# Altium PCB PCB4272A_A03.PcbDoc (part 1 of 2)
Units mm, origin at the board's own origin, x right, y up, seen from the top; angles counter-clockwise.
Board outline 32 x 51 mm, 4 copper layers (Top Layer, Signal Layer 2, Signal Layer 3, Bottom Layer), stack 1.6 mm thick; 110 components, 91 nets, 408 pads, 551 vias.
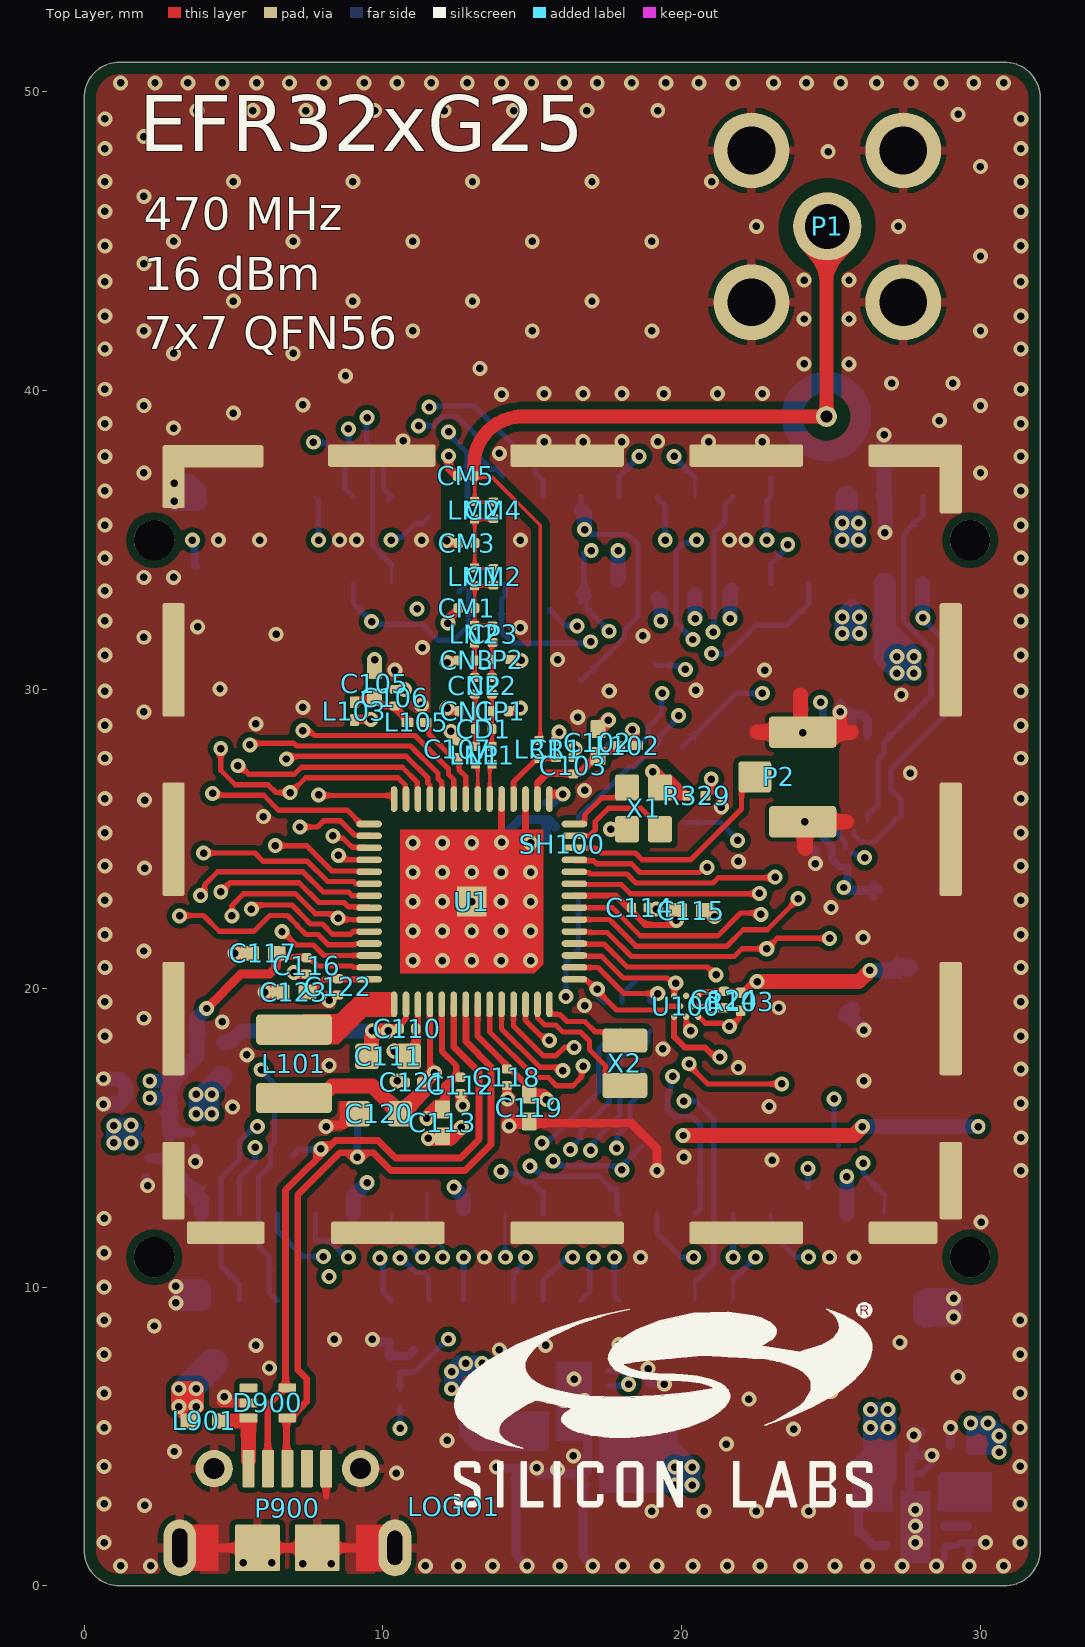
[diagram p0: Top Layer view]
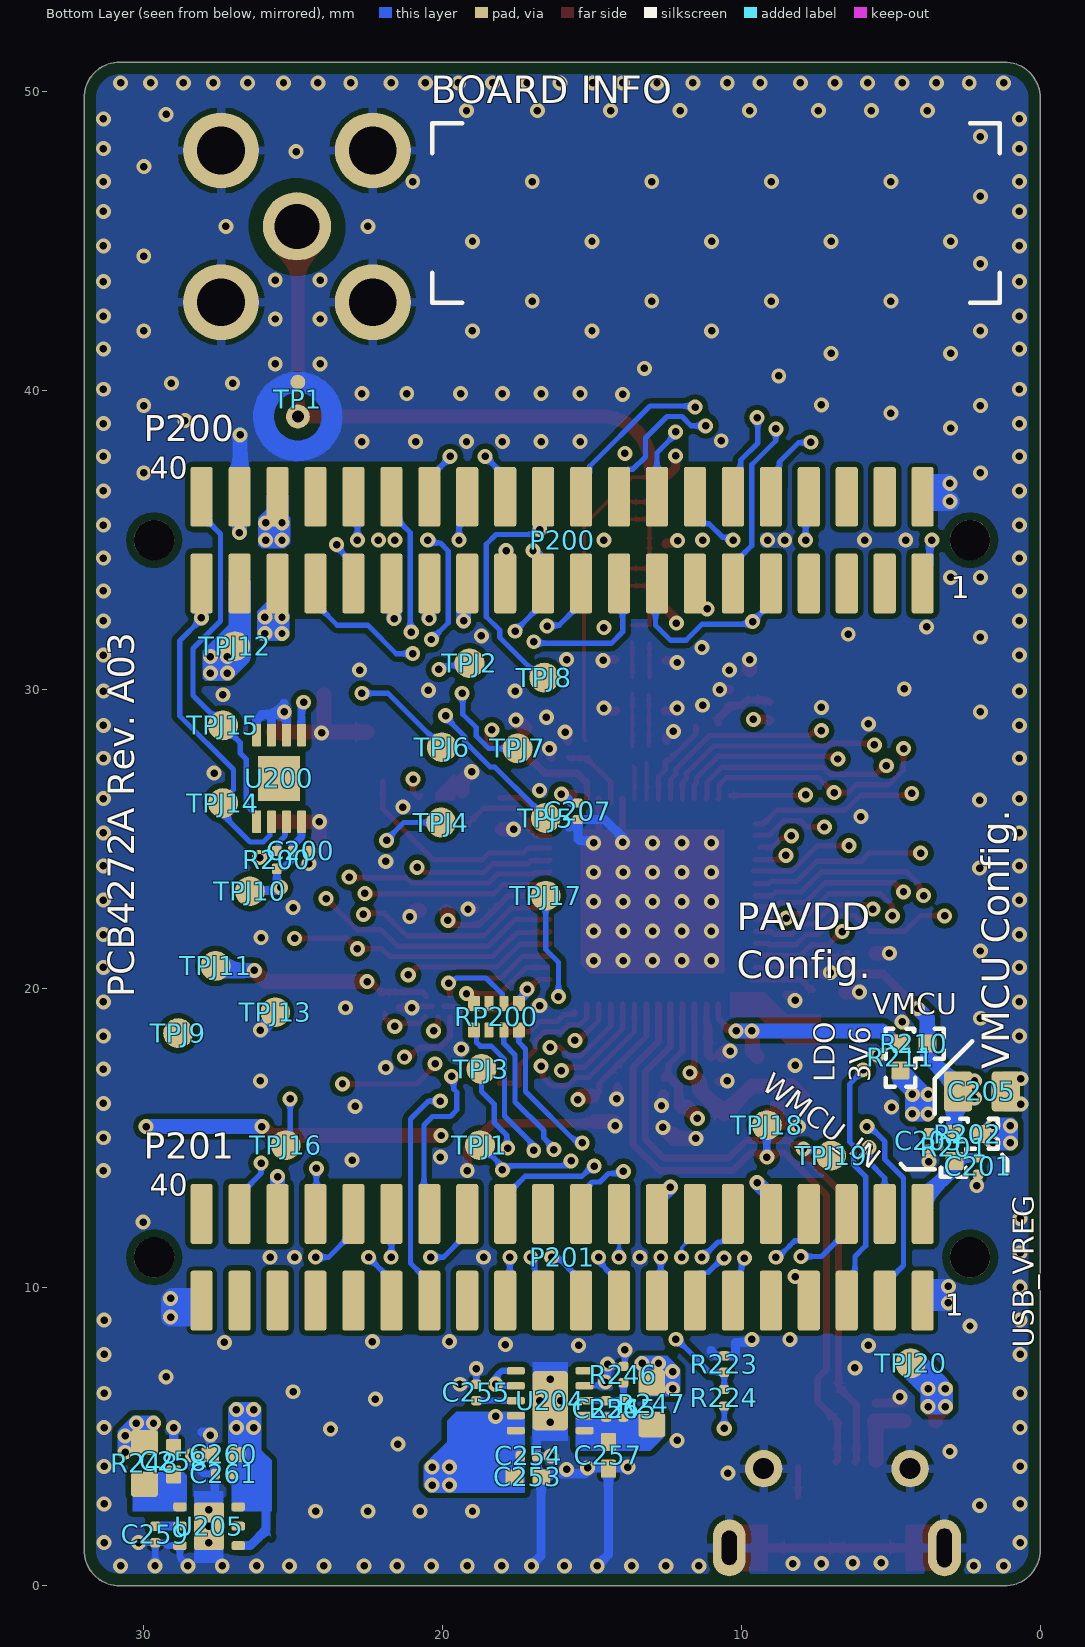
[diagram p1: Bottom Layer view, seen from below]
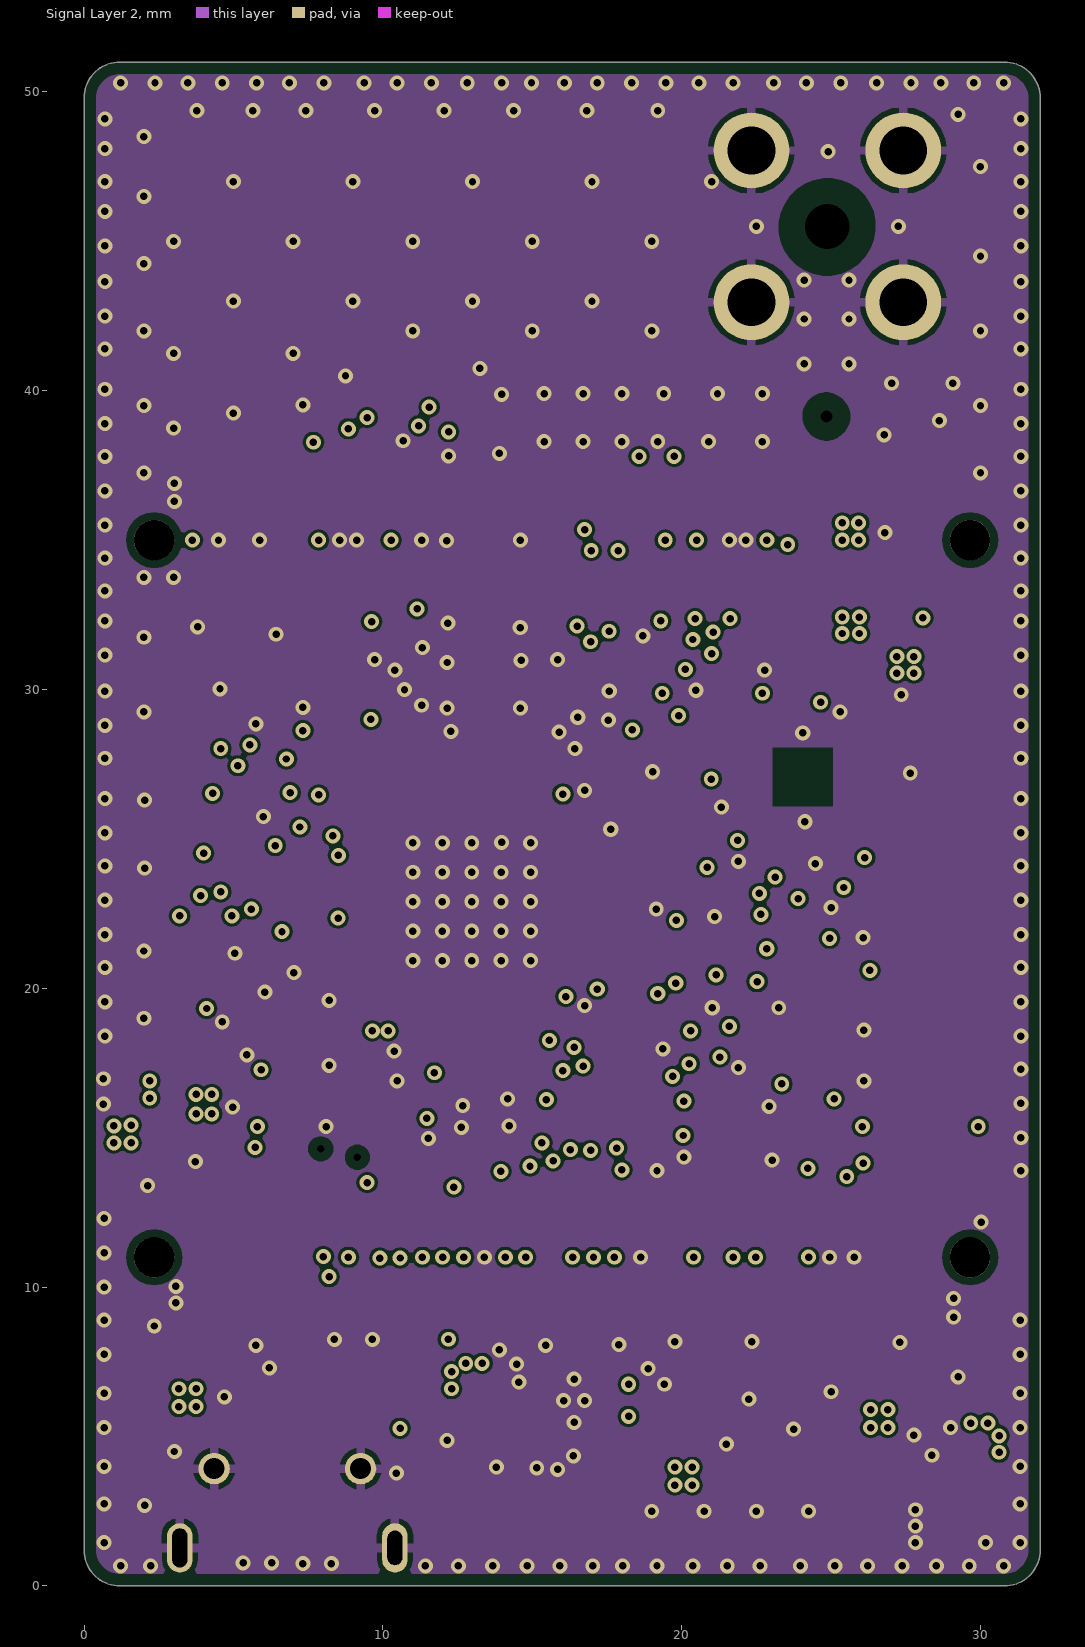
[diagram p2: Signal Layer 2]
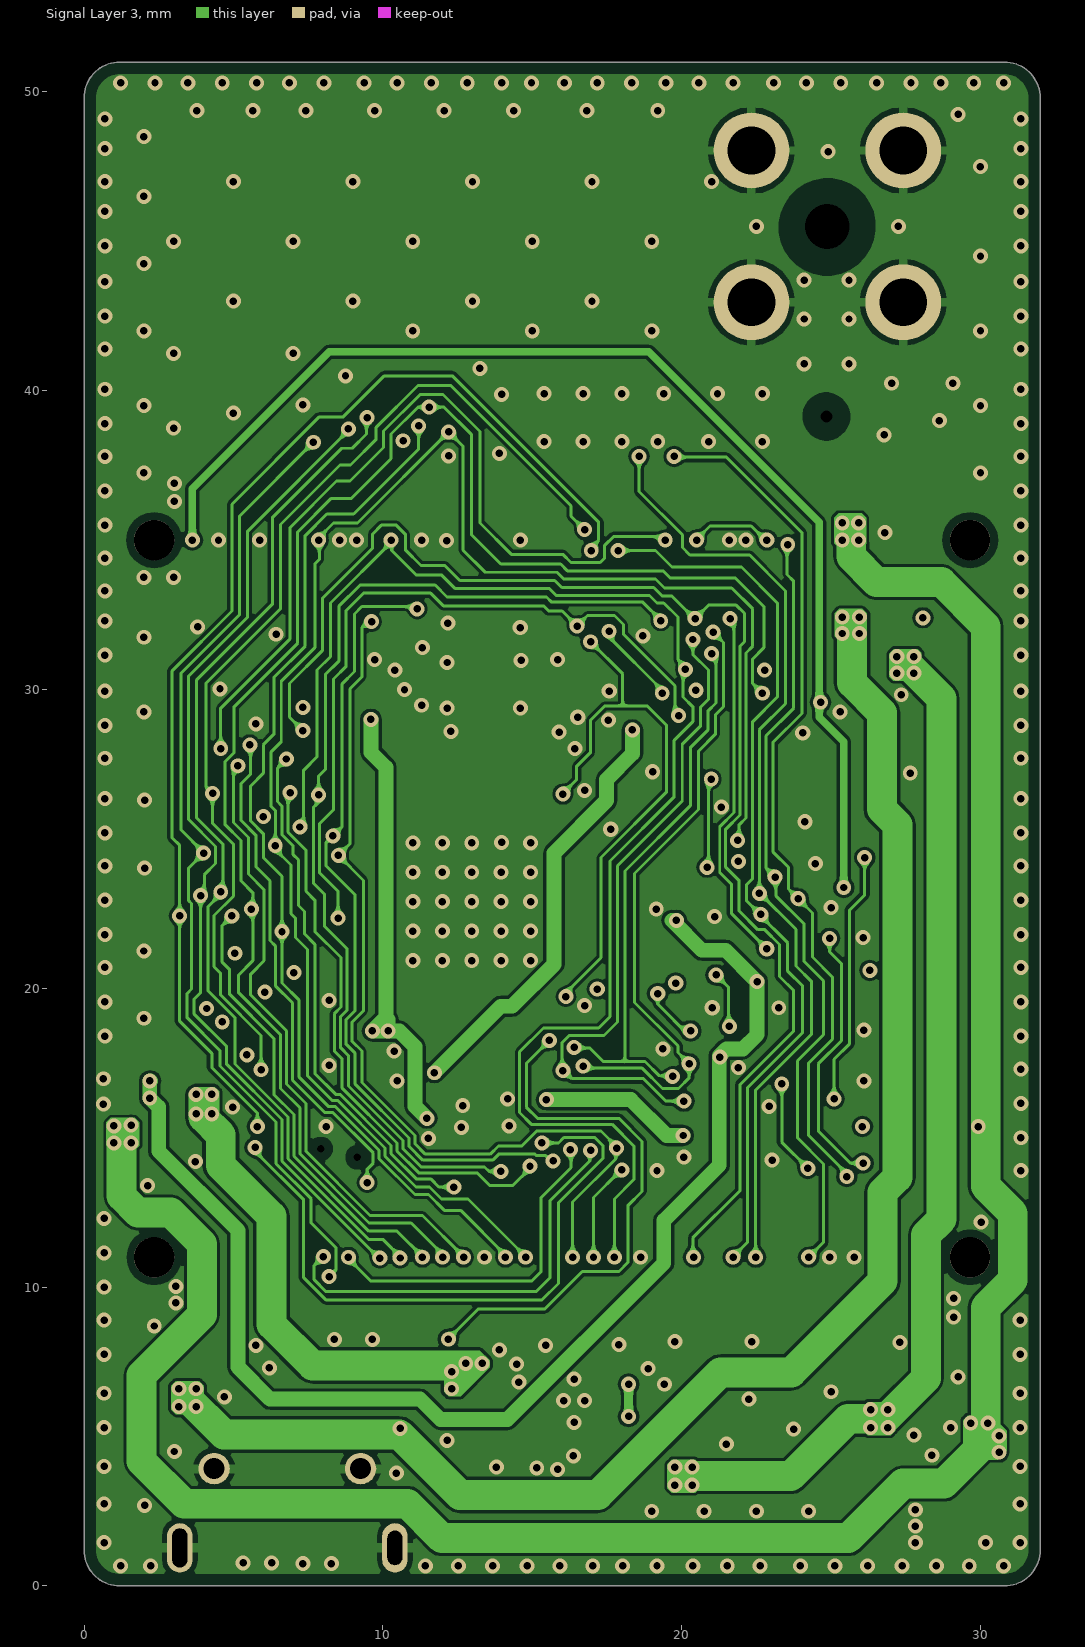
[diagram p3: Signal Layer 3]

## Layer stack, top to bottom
Top Solder: solder mask 0.0102, Solder Resist, Dk 3.5
Top Layer: signal copper 0.035
Dielectric 1: core 0.325, FR-4, Dk 4.2
Signal Layer 2: signal copper 0.018
Dielectric 3: prepreg 0.844, Dk 4.2
Signal Layer 3: signal copper 0.018
Dielectric 2: core 0.325, Dk 4.2
Bottom Layer: signal copper 0.035
Bottom Solder: solder mask 0.0102, Solder Resist, Dk 3.5

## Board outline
0,1.2 ccw(c1.2,1.2) 1.2,0 30.8,0 ccw(c30.8,1.2) 32,1.2 32,49.8 ccw(c30.8,49.8) 30.8,51 1.2,51 ccw(c1.2,49.8) 0,49.8

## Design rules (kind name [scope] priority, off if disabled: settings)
AcuteAngle [All] p1: minimum=7.00000000000000E+0001 checktracksonly=FALSE
BoardOutlineClearance [All] p1: gap=0.4 ignorepadtopadclearanceinfootprint=FALSE
Clearance [IsVia vs IsVia] p1: gap=0.175 ignorepadtopadclearanceinfootprint=FALSE except(0: Arc-Hole Track-Hole SMDPad-Hole THPad-Hole Via-Hole Fill-Hole Poly-Hole Region-Hole Text-Hole)
Clearance Clearance_50Ohm [InNetClass('50Ohm') vs InNet('GND')] p2: gap=0.254 ignorepadtopadclearanceinfootprint=FALSE except(0: Arc-Hole Track-Hole SMDPad-Hole THPad-Hole Via-Hole Fill-Hole Poly-Hole Region-Hole Text-Hole; 0.15: Track-SMDPad; 0.2: SMDPad-SMDPad)
Clearance Clearance_to_Holes [InPadClass('NPTH')] p3: gap=0.254 ignorepadtopadclearanceinfootprint=FALSE except(0: Arc-Hole Track-Hole SMDPad-Hole THPad-Hole Via-Hole Fill-Hole Poly-Hole Region-Hole Text-Hole)
Clearance Clearance_Outer_Layers [All vs OnLayer('Top Layer') or OnLayer('Bottom Layer')] p4: gap=0.175 ignorepadtopadclearanceinfootprint=FALSE except(0: Arc-Hole Track-Hole SMDPad-Hole THPad-Hole Via-Hole Fill-Hole Poly-Hole Region-Hole Text-Hole)
Clearance Clearance_Inner_Layers [All vs OnLayer('Signal Layer 2') or OnLayer('Signal Layer 3')] p5: gap=0.1 ignorepadtopadclearanceinfootprint=FALSE except(0: Arc-Hole Track-Hole SMDPad-Hole THPad-Hole Via-Hole Fill-Hole Poly-Hole Region-Hole Text-Hole; 0.175: Via-Via)
HoleToHoleClearance HoleToHoleClearance_ANT1toPAD [Incomponent ('ANT1') vs ISpad] p1: gap=0 allowstackedmicrovias=TRUE
HoleToHoleClearance HoleToHoleClearance_R1toR2_1 [Incomponent ('R1') vs Incomponent ('R2')] p2: gap=0 allowstackedmicrovias=TRUE
HoleToHoleClearance HoleToHoleClearance_U1toVIA_1 [InComponent ('U1') vs IsVia] p3: gap=0 allowstackedmicrovias=TRUE
HoleToHoleClearance [All] p4: gap=0.254 allowstackedmicrovias=TRUE
MinimumSolderMaskSliver [All] p1: minsoldermaskwidth=0.075
PolygonConnect Polygon_VIA_Connect [IsVia] p1: connectstyle=Direct reliefconductorwidth=0.254 reliefentries=4 polygonreliefangle="90 Angle" airgapwidth=0.254
PolygonConnect PolygonConnect_SH100 [InComponent('SH100')] p2: connectstyle=Direct reliefconductorwidth=0.254 reliefentries=4 polygonreliefangle="90 Angle" airgapwidth=0.127
PolygonConnect PolygonConnect_P1 [InComponent('P1') or InComponent('P900')] p3: connectstyle=Relief reliefconductorwidth=0.3 reliefentries=4 polygonreliefangle="90 Angle" airgapwidth=0.175
PolygonConnect [All] p4: connectstyle=NoConnect reliefconductorwidth=0.2 reliefentries=4 polygonreliefangle="90 Angle" airgapwidth=0.125
RoutingVias [All] p1: holewidth=0.3 width=0.65 viastyle="Through Hole" minholewidth=0.25 minwidth=0.5 maxholewidth=1 maxwidth=1.5
ShortCircuit ShortCircuit_ANTtoPAD [InNet('NetAT1_1') vs InNet('GND')] p1: allowed=TRUE
ShortCircuit ShortCircuit_R1toR2_1 [Incomponent ('R1') vs Incomponent ('R2')] p2: allowed=TRUE
ShortCircuit [All] p3: allowed=FALSE
SilkToSilkClearance [All] p1: silktosilkclearance=0.102
SilkToSolderMaskClearance [IsPad] p1: minsilkscreentomaskgap=0.102 clearancetoexposedcopper=TRUE
SolderMaskExpansion [All] p1: expansion=0.051 istentingtop=FALSE
Width 50ohm [InNet('50R*')] p1: maxlimit=0.457 minlimit=0.124 preferedwidth=0.457
Width [All] p2: maxlimit=5.08 minlimit=0.1 preferedwidth=0.125
25 further rules are at their usual default settings.

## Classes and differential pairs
pad class NPTH: P200-M1 P200-M2 P201-M1 P201-M2
net class 50Ohm: 50R_P1

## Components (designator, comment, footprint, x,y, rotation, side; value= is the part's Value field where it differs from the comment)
C102 "1U" C0402_L 17.2,28.225 r90 top
C103 "100P" C0201_L 16.375,27.45 r90 top
C105 "470N" C0402_L 9.725,30.2 r90 top
C106 "100P" C0201_L 10.4,29.725 r90 top
C107 "100P" C0201_L 12.5,28 r90 top
C110 "100N" C0201_L 10.825,18.65 r0 top
C111 "10U" C0603_L 10.175,17.725 r0 top
C112 "10N" C0201_L 12.6,16.75 r270 top
C113 "1U" C0402_L 12,15.5 r270 top
C114 "100N" C0201_L 18.6,22.7 r0 top
C115 "1U" C0402_L 20.325,22.6 r0 top
C116 "100N" C0201_L 7.45,20.75 r270 top
C117 "1U" C0402_L 6,21.175 r180 top
C118 "100N" C0201_L 14.15,17.025 r270 top
C119 "1U" C0402_L 14.9,16 r270 top
C120 "4U7" C0603_L 9.875,15.8 r180 top
C121 "100N" C0201_L 11.025,16.85 r180 top
C122 "100N" C0201_L 8.5,20.05 r270 top
C123 "1U" C0402_L 7.025,19.875 r180 top
C124 "100N" C0201_L 21.425,19.625 r270 top
C200 "100N" C0201_L 24.75,24.6 r180 bottom
C201 "100N" C0201_L 2.075,14.05 r270 bottom
C203 "100N" C0201_L 3.725,14.9 r270 bottom
C205 "10U" C0805_L 1.95,16.55 r180 bottom
C207 "100N" C0201_L 15.475,25.925 r270 bottom
C253 "1U" C0402_L 17.15,3.65 r180 bottom
C254 "100N" C0201_L 17.125,4.35 r180 bottom
C255 "100N" C0201_L 18.875,6.475 r90 bottom
C256 "10N" C0201_L 14.525,5.925 r90 bottom
C257 "10U" C0402_L 14.45,4.375 r270 bottom
C258 "2U2" C0402_L 29,4.175 r90 bottom
C259 "100N" C0201_L 29.615,1.725 r270 bottom
C260 "1U" C0402_L 27.325,4.4 r0 bottom
C261 "100N" C0201_L 27.325,3.75 r0 bottom
CD1 "Unused" C0201_L 13.375,28.675 r0 top
CM1 "8P0" C0201_L 12.8,32.725 r180 top
CM2 "Unused" C0201_L 13.7,33.775 r90 top
CM3 "9P5" C0201_L 12.8,34.9 r180 top
CM4 "Unused" C0201_L 13.7,36 r90 top
CM5 "5P0" C0201_L 12.775,37.15 r180 top
CN1 "18P" C0201_L 12.825,29.275 r180 top
CN2 "220P" C0201_L 13.075,30.125 r90 top
CN3 "9P0" C0201_L 12.8,30.975 r0 top
CP1 "20P" C0201_L 13.925,29.275 r0 top
CP2 "220P" C0201_L 13.65,30.125 r270 top
CP3 "7P0" C0201_L 13.675,31.85 r270 top
CR1 "Unused" C0201_L 15.8,27.997 r90 top
D900 "SP1001-04" SOT553_L 6.15,6.125 r0 top
Designator39 "Comment" PCB_SPEC_4_LAYER -67.7,114.2 r0 top
L101 "2U2" COIL_1008_L 7.025,17.475 r270 top
L102 "BLM03AG700SN1D" COIL_MUR_BLM03_0201 18.2,28.125 r180 top
L103 "0R" COIL_MUR_BLM03_0201 9.05,29.275 r90 top
L105 "BLM03PG330SN1D" COIL_MUR_BLM03_0201 11.125,28.9 r0 top
L901 "782422221" COIL_0402 4.025,5.525 r180 top
LM1 "13N" COIL_0201_L 13.075,33.775 r90 top
LM2 "16N" COIL_0201_L 13.075,36 r90 top
LN1 "4N2" COIL_0201_L 13.1,27.8 r90 top
LN2 "16N" COIL_0201_L 13.075,31.85 r90 top
LOGO1 "Comment" LOGO_SILABS_W14.0 12.375,2.65 r0 top
LP1 "4N2" COIL_0201_L 13.65,27.8 r90 top
LP2 "16N" COIL_0201_L 13.95,31 r180 top
LR1 "68N" COIL_0201_L 15.225,27.997 r90 top
P1 "SMA" TE_SMA_1814832_TH_VER 24.875,45.5 r0 top
P2 "U.FL" HIROSE_U.FL-R-SMT-1 24.05,27.075 r90 top
P200 "SOCKET_WCON_2X20_1.27MM_SMD" SAM_SFC-120-T2-D-A-2X20_SNUM 16,35 r0 bottom locked
P201 "SOCKET_WCON_2X20_1.27MM_SMD" SAM_SFC-120-T2-D-A-2X20_SNUM 16,11 r0 bottom locked
P900 "USB MICRO-B" KLS_L-KLS1-238-0-X-0-X 6.805,-0.475 r0 top
R103 "330K" R0201_L#1 21.975,19.55 r90 top
R200 "10K" R0201_L#1 25.55,24.3 r270 bottom
R201 "0R" R0402_L 2.875,14.675 r270 bottom
R202 "0R" R0402_L 2.425,15.125 r180 bottom
R210 "0R" R0402_L 4.225,18.15 r0 bottom
R211 "0R" R0402_L 4.675,17.7 r90 bottom
R223 "680K" R0201_L#2 10.575,7.425 r270 bottom
R224 "390K" R0201_L#2 10.575,6.3 r270 bottom
R245 "4.02k" R0201_L#2 13.95,5.925 r270 bottom
R246 "1.15k" R0201_L#2 13.95,7.075 r270 bottom
R247 "0R" R0603_L 13,6.1 r90 bottom
R248 "0R" R0603_L 29.975,4.1 r90 bottom
R329 "100K" R0201_L#1 20.5,26.45 r180 top
RP200 "100R" RES_MNR04-8 18.2,19.05 r0 bottom
SH100 "RF_SHIELD_FRAME_BMI-S-203-F" RF_SHIELD_FRAME_BMI-S-203-F_PCB4270 16,24.825 r0 top locked
TP1 "TP_RF" "TP_INGUN_50_OHM_CLOSED OPENVIA" 24.845,39.135 r0 bottom
TPJ1 "TPJ_SMD" TP_1.0_SMD 18.75,14.75 r90 bottom locked
TPJ2 "TPJ_SMD" TP_1.0_SMD 19.1,30.88 r90 bottom locked
TPJ3 "TPJ_SMD" TP_1.0_SMD 18.7,17.3 r90 bottom locked
TPJ4 "TPJ_SMD" TP_1.0_SMD 20.05,25.55 r90 bottom locked
TPJ5 "TPJ_SMD" TP_1.0_SMD 16.55,25.7 r90 bottom locked
TPJ6 "TPJ_SMD" TP_1.0_SMD 20.02,28.07 r90 bottom locked
TPJ7 "TPJ_SMD" TP_1.0_SMD 17.49,28.03 r90 bottom locked
TPJ8 "TPJ_SMD" TP_1.0_SMD 16.6,30.4 r90 bottom locked
TPJ9 "TPJ_SMD" TP_1.0_SMD 28.85,18.5 r90 bottom locked
TPJ10 "TPJ_SMD" TP_1.0_SMD 26.45,23.25 r90 bottom locked
TPJ11 "TPJ_SMD" TP_1.0_SMD 27.6,20.75 r90 bottom locked
TPJ12 "TPJ_SMD" TP_1.0_SMD 26.95,31.45 r90 bottom locked
TPJ13 "TPJ_SMD" TP_1.0_SMD 25.6,19.2 r90 bottom locked
TPJ14 "TPJ_SMD" TP_1.0_SMD 27.35,26.2 r90 bottom locked
TPJ15 "TPJ_SMD" TP_1.0_SMD 27.35,28.8 r90 bottom locked
TPJ16 "TPJ_SMD" TP_1.0_SMD 25.25,14.75 r90 bottom locked
TPJ17 "TPJ_SMD" TP_1.0_SMD 16.55,23.1 r90 bottom locked
TPJ18 "TPJ_SMD" TP_1.0_SMD 9.15,15.42 r90 bottom locked
TPJ19 "TPJ_SMD" TP_1.0_SMD 7,14.4 r90 bottom locked
TPJ20 "TPJ_SMD" TP_1.0_SMD 4.34,7.45 r90 bottom locked
U1 "EFR32FG25B222F1920IM56" QFN56_M040_7.0X7.0_EP_SL 12.975,22.9 r180 top
U100 "MX25R8035F" BGA8_M040_1.24x1.75_WLCSP 20.15,19.4 r270 top
U200 "24AA024" TDFN8_M050_2.0X3.0_EP 25.475,27.025 r270 bottom
U204 "TPS7A92" WFDFN-10_EP_TPS7A92 16.4,6.2 r0 bottom
U205 "TPS79933DRVR" SON-6_EP_TPS79933DDCR 27.815,2 r180 bottom
X1 "39.000 MHz" KDS_DSX211SH_2016 18.725,26.025 r270 top
X2 "32.768 kHz" X_MCS_CM8V-T1A 18.1,17.5 r270 top

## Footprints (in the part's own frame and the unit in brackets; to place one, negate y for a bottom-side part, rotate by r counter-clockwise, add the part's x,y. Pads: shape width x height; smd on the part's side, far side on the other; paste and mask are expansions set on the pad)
BGA8_M040_1.24x1.75_WLCSP [mm] "BGA, 8 pin. U100"
  round 0.21 smd mask+0.051: A1(-0.35,0.4) A3(0.35,0.4) B2(0,0.2) C1(-0.35,0) C3(0.35,0) D2(0,-0.2) E1(-0.35,-0.4) E3(0.35,-0.4)
  body extent -0.63,-0.89 0.63,0.88, height 0.52
C0201_L [mm] "Capacitor, Chip; 0.60 mm L X 0.30 mm W X 0.33 mm H body"
  rrect52% 0.31x0.34 smd: 1(-0.275,0) 2(0.275,0)
  body extent -0.3,-0.15 0.3,0.15, height 0.3
C0402_L [mm] "Chip Capacitor, 2-Leads, Body 1.0x0.5mm, IPC High Density"
  rrect20% 0.6x0.5 smd mask+0.051: 1(-0.45,0) 2(0.45,0)
  body extent -0.5,-0.25 0.5,0.25, height 0.6
C0603_L [mm] "Capacitor, 0603, High Density (C)"
  rrect25% 0.8x0.85 smd: 1(-0.7,0) 2(0.7,0)
  body extent -0.8,-0.4 0.8,0.4, height 0.95
C0805_L [mm] "Capacitor, 0805"
  rrect25% 0.95x1.35 smd: 1(-0.8,0) 2(0.8,0)
  body extent -1.1,-0.72 1.1,0.72, height 1.45
COIL_0201_L [mm] "JELF243C-0021"
  rrect10% 0.3x0.3 smd: 1(-0.3,0) 2(0.3,0)
  body extent -0.32,-0.17 0.32,0.17, height 0.33
COIL_0402 [mm] "COIL_0402_L (3D from Wurth) (190308)"
  rrect20% 0.55x0.5 smd mask+0.051: 1(-0.525,0) 2(0.525,0)
  body extent -0.5,-0.25 0.5,0.25, height 0.5
COIL_1008_L [mil] "Chip Inductors, 1008 (2520), Coilcraft (190207)"
  rrect25% 40x100 smd: 1(-45,0) 2(45,0)
  body extent -58,-55 57,55, height 80
COIL_MUR_BLM03_0201 [mm] "COIL_MUR_BLM03_0201"
  rrect25% 0.4x0.3 smd mask+0.051: 1(-0.3,0) 2(0.3,0)
  body extent -0.3,-0.15 0.3,0.15, height 0.95
HIROSE_U.FL-R-SMT-1 [mm] "COAX_HIROSE_U.FL_CL331-0471"
  rrect20% 1.05x1.1 smd mask+0.051: 1(0,1.6)
  rrect20% 1.05x2.25 smd mask+0.051: 2(-1.5,0) 3(1.5,0)
  Top Layer pour cut-out: -0.85,0.9 0.85,0.9 0.85,0.9 0.85,-1.2 -0.85,-1.2 -0.85,-1.2
  body extent -1.3,-1.55 1.3,1.3, height 0.9
KDS_DSX211SH_2016 [mm] "Copy of Silabs CE  X_KDS_DSX211SH_2.0X1.65-4"
  rrect20% 0.875x0.8 smd mask+0.051: 1(-0.7,-0.55) 2(0.7,-0.55) 3(0.7,0.55) 4(-0.7,0.55)
  body extent -1.07,-0.87 1.08,0.88, height 0.5
KLS_L-KLS1-238-0-X-0-X [mm] "Amphenol FCI, 10118194-000XLF, Micro USB Type B (171108)"
  rrect20% 0.4x1.25 smd mask+0.076: 1(-1.3,4.4) 2(-0.65,4.4) 3(0,4.4) 4(0.65,4.4) 5(1.3,4.4)
  round 1.25 / inner round 1.05 / far side round 1.25 hole 0.7 mask+0.051: 6(-2.45,4.4) 7(2.45,4.4)
  oval 1.1x1.9 / inner oval 0.85x1.65 / far side oval 1.1x1.9 hole 0.5 slot 1.3 at 90 deg paste+0 mask+0.051: 8(-3.6,1.75)
  oval 1.1x1.9 / inner oval 0.85x1.65 / far side oval 1.1x1.9 hole 0.5 slot 1.15 at 90 deg paste+0 mask+0.051: 9(3.6,1.75)
  rrect5% 1.5x1.55 smd: 10(-1,1.75) 11(1,1.75)
  Top Layer region: -3.501,0.976 -2.33,0.976 -2.306,1 -2.305,2.503 -2.33,2.528 -3.497,2.528 -3.587,2.528 -3.754,2.459 -3.881,2.331 -3.95,2.165 -3.95,2.075 -3.95,1.425 -3.95,1.336 -3.882,1.171 -3.755,1.044 -3.59,0.976
  Top Layer region: 3.501,2.524 2.33,2.524 2.306,2.5 2.305,0.997 2.33,0.972 3.497,0.972 3.587,0.972 3.754,1.041 3.881,1.169 3.95,1.335 3.95,1.425 3.95,2.075 3.95,2.164 3.882,2.329 3.755,2.456 3.59,2.524
  body extent -4.05,-0.88 4,4.7, height 3.12
LOGO_SILABS_W14.0 [mm] "LOGO_SILABS_W14.0"
  silkscreen extent 0.03,0 13.99,6.83
PCB_SPEC_4_LAYER [mm]
QFN56_M040_7.0X7.0_EP_SL [mm]
  rect 1x1 smd: 0(0,0)
  oval 0.86x0.22 smd: 1(-3.435,2.6) 2(-3.435,2.2) 3(-3.435,1.8) 4(-3.435,1.4) 5(-3.435,1) 6(-3.435,0.6) 7(-3.435,0.2) 8(-3.435,-0.2) 9(-3.435,-0.6) 10(-3.435,-1) 11(-3.435,-1.4) 12(-3.435,-1.8) 13(-3.435,-2.2) 14(-3.435,-2.6) 29(3.435,-2.6) 30(3.435,-2.2) 31(3.435,-1.8) 32(3.435,-1.4) 33(3.435,-1) 34(3.435,-0.6) 35(3.435,-0.2) 36(3.435,0.2) 37(3.435,0.6) 38(3.435,1) 39(3.435,1.4) 40(3.435,1.8) 41(3.435,2.2) 42(3.435,2.6)
  oval 0.22x0.86 smd: 15(-2.6,-3.435) 16(-2.2,-3.435) 17(-1.8,-3.435) 18(-1.4,-3.435) 19(-1,-3.435) 20(-0.6,-3.435) 21(-0.2,-3.435) 22(0.2,-3.435) 23(0.6,-3.435) 24(1,-3.435) 25(1.4,-3.435) 26(1.8,-3.435) 27(2.2,-3.435) 28(2.6,-3.435) 43(2.6,3.435) 44(2.2,3.435) 45(1.8,3.435) 46(1.4,3.435) 47(1,3.435) 48(0.6,3.435) 49(0.2,3.435) 50(-0.2,3.435) 51(-0.6,3.435) 52(-1,3.435) 53(-1.4,3.435) 54(-1.8,3.435) 55(-2.2,3.435) 56(-2.6,3.435)
  Top Layer pour cut-out: -3,-2.675 -2.675,-3 2.725,-3 3,-2.725 3,2.75 2.75,3 -2.725,3 -3,2.725
  Top Layer region: 2.4,-2.4 -2.4,-2.4 -2.4,2.1 -2.1,2.4 2.4,2.4
  body extent -3.5,-3.5 3.5,3.5, height 0.86
R0201_L#1 [mm] "Resistor (Chip2PinSM127P600-8N) (170921)"
  rrect25% 0.34x0.32 smd: 1(-0.3,0) 2(0.3,0)
  body extent -0.32,-0.13 0.32,0.13, height 0.3
R0201_L#2 [mm] "Resistor, Chip; 0.60 mm L X 0.30 mm W X 0.28 mm H body"
  rrect52% 0.31x0.34 smd: 1(-0.275,0) 2(0.275,0)
  body extent -0.3,-0.15 0.3,0.15, height 0.23
R0402_L [mm] "Chip Resistor, 2-Leads, Body 1.0x0.5mm, IPC High Density"
  rrect20% 0.6x0.6 smd mask+0.051: 1(-0.45,0) 2(0.45,0)
  body extent -0.5,-0.25 0.5,0.25, height 0.6
R0603_L [mm] "Chip Resistor, 0603, High density, Level C (_L) (170210)"
  rrect25% 0.85x0.9 smd: 1(-0.7,0) 2(0.7,0)
  body extent -0.8,-0.4 0.8,0.4, height 0.95
RES_MNR04-8 [mm] "Chip resistor network 8pin"
  rrect20% 0.4x0.5 smd mask+0.051: 1(-0.75,-0.45) 4(0.75,-0.45) 5(0.75,0.45) 8(-0.75,0.45)
  rrect20% 0.3x0.5 smd mask+0.051: 2(-0.25,-0.45) 3(0.25,-0.45) 6(0.25,0.45) 7(-0.25,0.45)
  body extent -1,-0.4 1,0.4, height 0.5
RF_SHIELD_FRAME_BMI-S-203-F_PCB4270 [mm] "RF_SHIELD_FRAME_BMI-S-203-F"
  rrect20% 0.75x3.8 smd paste+0 mask+0.05: 1(-13.005,-5.835) 1(-13.005,0.165) 1(-13.005,6.165) 1(13.005,-5.835) 1(13.005,0.165) 1(13.005,6.165)
  rrect20% 0.75x2.6 smd paste+0 mask+0.05: 1(-13.005,-11.259) 1(13.005,-11.259)
  rrect20% 0.75x2.1 smd paste+0 mask+0.05: 1(-13.005,12.294)
  oval 0.75x0.254 smd paste+0 mask+0.05: 1(-13.004,12.994) 1(12.994,12.994) 1(12.994,12.994) 1(12.994,12.994)
  rrect20% 3.375x0.75 smd paste+0 mask+0.05: 1(-11.684,12.979)
  rrect20% 2.6x0.75 smd paste+0 mask+0.05: 1(-11.259,-13.005)
  rrect20% 3.6x0.75 smd paste+0 mask+0.05: 1(-6.035,13.005)
  rrect20% 3.8x0.75 smd paste+0 mask+0.05: 1(-5.835,-13.005) 1(0.165,-13.005) 1(0.165,13.005) 1(6.165,-13.005) 1(6.165,13.005)
  rrect20% 2.3x0.75 smd paste+0 mask+0.05: 1(11.411,-13.005)
  rrect20% 3.125x0.75 smd paste+0 mask+0.05: 1(11.811,13.005)
  rrect20% 0.75x2.3 smd paste+0 mask+0.05: 1(13.005,12.217)
  body extent -13.3,-13.3 13.3,13.3, height 5.5
SAM_SFC-120-T2-D-A-2X20_SNUM [mm]
  rrect20% 0.74x2 smd mask+0.05: 1(-12.065,1.45) 2(-12.065,-1.45) 3(-10.795,1.45) 4(-10.795,-1.45) 5(-9.525,1.45) 6(-9.525,-1.45) 7(-8.255,1.45) 8(-8.255,-1.45) 9(-6.985,1.45) 10(-6.985,-1.45) 11(-5.715,1.45) 12(-5.715,-1.45) 13(-4.445,1.45) 14(-4.445,-1.45) 15(-3.175,1.45) 16(-3.175,-1.45) 17(-1.905,1.45) 18(-1.905,-1.45) 19(-0.635,1.45) 20(-0.635,-1.45) 21(0.635,1.45) 22(0.635,-1.45) 23(1.905,1.45) 24(1.905,-1.45) 25(3.175,1.45) 26(3.175,-1.45) 27(4.445,1.45) 28(4.445,-1.45) 29(5.715,1.45) 30(5.715,-1.45) 31(6.985,1.45) 32(6.985,-1.45) 33(8.255,1.45) 34(8.255,-1.45) 35(9.525,1.45) 36(9.525,-1.45) 37(10.795,1.45) 38(10.795,-1.45) 39(12.065,1.45) 40(12.065,-1.45)
  round 1.35 hole 1.35 unplated paste-5.563 mask-5.563: M1(13.652,0) M2(-13.652,0)
  body extent -14.29,-2.1 14.29,2.16, height 4.67
SON-6_EP_TPS79933DDCR [mm]
  rrect50% 0.45x0.3 smd mask+0.05: 1(-0.975,0.65) 2(-0.975,0) 3(-0.975,-0.65) 4(0.975,-0.65) 5(0.975,0) 6(0.975,0.65)
  rrect15% 1x1.6 smd paste-2 mask+0.05: 7(0,0)
  rrect25% 1x0.7 on Bottom Paste paste+0: ""(0,-0.45) ""(0,0.45)
  body extent -1.04,-1.04 1.04,1.04, height 0.76
SOT553_L [mm] "SOT553 (_M050_W1.2_), 5-Leads, Body 1.60x1.20mm, Pitch 0.5mm, HiDens (180615)"
  rrect25% 0.6x0.3 smd: 1(-0.65,0.5) 2(-0.65,0) 3(-0.65,-0.5) 4(0.65,-0.5) 5(0.65,0.5)
  body extent -0.65,-0.85 0.65,0.85, height 0.6
TDFN8_M050_2.0X3.0_EP [mm] "TDFN8_M050_2.0x3.0_EP"
  rrect20% 0.75x0.3 smd mask+0.051: 1(-1.45,0.75) 2(-1.45,0.25) 3(-1.45,-0.25) 4(-1.45,-0.75) 5(1.45,-0.75) 6(1.45,-0.25) 7(1.45,0.25) 8(1.45,0.75)
  rect 1.5x1.4 smd mask+0.051: 9(0,0)
  body extent -1.5,-1 1.5,1, height 1.01
TE_SMA_1814832_TH_VER [mm]
  round 2.286 / inner round 0 / far side round 2.286 hole 1.5: 1(0,0)
  round 2.54 hole 1.6: 2(-2.54,-2.54) 3(2.54,-2.54) 4(2.54,2.54) 5(-2.54,2.54)
  body extent -3.2,-3.2 3.2,3.2, height 9.5
TP_1.0_SMD [mm] "Test Point, 1.0 mm, SMD"
  round 1 smd paste-0.501: 1(0,0)
  body extent -0.2,-0.2 0.2,0.2, height 0.01
"TP_INGUN_50_OHM_CLOSED OPENVIA" [mm] "TP_INGUN_50_OHM_CLOSED"
  round 0.8 / inner round 0 / far side round 0.7 hole 0.4 mask+0: 1(0,0)
  round 0.5 smd paste-0.255 mask-0.41: 2(0,-1.15)
  Top Layer pour cut-out: 0,-0.8 0.4,-0.693 0.693,-0.4 0.8,0 0.693,0.4 0.4,0.693 0,0.8 0,0.8 -0.347,0.721 -0.625,0.499 -0.78,0.178 -0.78,-0.178 -0.625,-0.499 -0.347,-0.721 0,-0.8
  Top Layer lines w0.7: -1.15,0 cw(c0,0) 0,-1.15 cw(c0,0) -1.15,0
WFDFN-10_EP_TPS7A92 [mm]
  rrect50% 0.6x0.25 smd mask+0.05: 1(-1.15,1) 2(-1.15,0.5) 3(-1.15,0) 4(-1.15,-0.5) 5(-1.15,-1) 6(1.15,-1) 7(1.15,-0.5) 8(1.15,0) 9(1.15,0.5) 10(1.15,1)
  rrect25% 1.2x2 smd paste-2 mask+0.05: 11(0,0)
  rrect15% 1.13x0.89 on Bottom Paste paste+0: ""(0,-0.525) ""(0,0.525)
  body extent -1.25,-1.25 1.25,1.25, height 0.76
X_MCS_CM8V-T1A [mm] "Crystal MCS CM8V-T1A (2 pin)"
  rrect25% 0.8x1.5 smd mask+0.051: 1(-0.75,0)
  rrect25% 0.85x1.5 smd mask+0.051: 2(0.75,0)
  body extent -1,-0.6 1,0.6, height 0.95

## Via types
v1: diameter 0.5, hole 0.25, Top Layer to Bottom Layer, tented both sides, 512 vias
v2: diameter 0.508, hole 0.25, Top Layer to Bottom Layer, tented both sides, 37 vias
v3: diameter 0.5/0/0/0.5 (per signal layer), hole 0.25, Top Layer to Bottom Layer, tented both sides, 2 vias

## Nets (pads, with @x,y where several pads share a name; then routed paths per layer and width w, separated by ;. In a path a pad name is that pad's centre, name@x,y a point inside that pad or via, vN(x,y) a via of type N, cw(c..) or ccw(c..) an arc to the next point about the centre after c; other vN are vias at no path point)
3V3: C200.1 P200.1 R200.2 TPJ10.1 U200.1 U200.8 | length 46.4
  Signal Layer 3 w0.254: v1(3.625,35) 3.625,36.725 8.2,41.3 18.9,41.3 24.6,35.6 24.6,29.075 25.425,28.25 v1(25.425,23.375)
  Bottom Layer w0.254: v1(3.625,35) 3.625,35.05 3.588,35.013 3.7,34.9 3.7,34.175 P200.1@3.75,34.125 ; v1@24.625,29.575 24.638,29.563 24.663,29.587 24.725,29.525 U200.1@24.725,28.275 ; U200.8@24.725,25.575 24.725,25.055 24.932,24.848 24.932,24.843 25,24.775 25.025,24.775 ; C200.1@25.025,24.75 25.027,24.748 25.027,24.323 25.3,24.05 R200.2@25.525,24.05 ; v1@25.55,23.375 R200.2@25.55,24 25.55,24.01 R200.2@25.575,24.035
  Bottom Layer w0.305: v1(25.425,23.375) 25.525,23.275 TPJ10.1@26.425,23.275 ; TPJ10.1@26.425,23.1 TPJ10.1@26.425,23.275 ; TPJ10.1@26.425,23.275 26.425,23.45 26.6,23.275 TPJ10.1@26.425,23.275
  other v1: 24.65,29.575
5V: C253.1 C254.1 C260.1 C261.1 P200.37 TPJ12.1 U204.6 U204.7 U204.9 U204.10 U205.4 U205.6 | length 43.3
  Signal Layer 3 w0.3: v2(18.225,5.675) v2(18.225,6.75) v2@18.225,6.775
  Signal Layer 3 w1: 20.15,3.7 20.175,3.675 23.65,3.675 25.571,5.596 26.821,5.596 28.175,6.95 28.175,11.75 28.7,12.275 28.7,29.7 27.575,30.825
  Bottom Layer w0.2: U204.7@17.55,6.7 18.225,6.7 v2(18.225,6.75) 18.225,7 18.025,7.2 U204.6@17.55,7.2
  Bottom Layer w0.3: U205.4@26.84,1.35 26.44,1.35 25.915,1.875 25.915,2.825 26.09,2.65 U205.6@26.84,2.65
  Bottom Layer w0.75: P200.37@26.795,33.55 26.795,31.13 27.25,30.675 v1@27.575,30.675
  other v1: 19.775,3.375 20.35,3.375 19.775,3.975 20.35,3.975 26.325,5.3 26.9,5.3 26.325,5.9 26.9,5.9 27.2,30.55 27.775,30.55 27.2,31.1 27.775,31.1
50R_P1: CM4.2 CM5.1 LM2.2 LR1.2 P1.1 TP1.1 | length 31.1
  Top Layer w0.125: CM5.1@13.05,37.1 CM5.1@13.075,37.1 ; CM4.2@13.675,36.3 13.65,36.275 13.075,36.275 LM2.2@13.075,36.3 CM5.1@13.075,37.1 ; LR1.2@15.22,28.297 15.271,28.349 15.271,35.499 13.67,37.1 CM5.1@13.075,37.1
  Top Layer w0.35: CM5.1@13.05,37.175 13.05,37.45 13.05,37.475
  Top Layer w0.457: 13.05,37.45 cw(c14.658,37.524) 14.658,39.134 ; 14.55,39.135 TP1.1@24.845,39.135 P1.1@24.845,45.5
BOARD_ID_SCL: P200.39 TPJ14.1 U200.6 | length 11.1
  Bottom Layer w0.175: U200.6@25.775,25.251 25.775,25.125 26,24.9 26.45,24.9 27.35,25.8 TPJ14.1@27.35,26.2 27.35,26.3 27,26.65 27,27.325 28.8,29.125 28.8,31.625 28.075,32.35 v1(28.075,32.4)
  Bottom Layer w0.5: P200.39@28.065,33.55 28.065,32.41 v1(28.075,32.4)
BOARD_ID_SDA: P200.40 TPJ15.1 U200.5 | length 12.4
  Bottom Layer w0.102: U200.5@26.225,25.575 U200.5@26.225,25.8 ; TPJ15.1@27.3,28.725 TPJ15.1@27.325,28.725
  Bottom Layer w0.175: U200.5@26.225,25.8 26.575,26.15 26.575,27.675 26.775,27.875 26.775,28.225 TPJ15.1@27.35,28.8 28.35,29.8 28.35,31.375 27.433,32.292 27.433,35.208 P200.40@28.025,35.8 ; P200.40@28.038,35.788 P200.40@28.065,35.815 ; P200.40@28.065,36.45 P200.40@28.065,35.815 ; P200.40@28.075,35.825 P200.40@28.065,35.815
BOARD_ID_WP: R200.1 TPJ16.1 U200.7 | length 11.2
  Signal Layer 3 w0.1: v1(25.1,16.3) 25.1,17.625 25.625,18.15 25.625,22.625 26.126,23.126 v1(26.126,24.376)
  Bottom Layer w0.1: v1@26.05,24.25 26.126,24.326 v1(26.126,24.376)
  Bottom Layer w0.175: TPJ16.1@25.1,14.95 v1(25.1,16.3) ; U200.7@25.225,25.325 25.275,25.275 25.275,25.1 25.475,24.9 R200.1@25.475,24.7 ; R200.1@25.7,24.525 25.775,24.525 v1@26.05,24.25
EFR32_PA0: P200.22 P201.5 TPJ8.1 U1.29 | length 58.8
  Top Layer w0.175: v1(4.3,26.525) 4.363,26.462 6.013,26.462 6.513,25.962 8.813,25.962 9.275,25.5 U1.29@9.54,25.5
  Signal Layer 3 w0.1: v1(5.925,17.276) 5.925,18.425 4.575,19.775 4.575,20.5 4.35,20.725 4.35,22.435 5,23.085 5,24.825 4.3,25.525 v1(4.3,26.525) 4.075,26.75 4.075,30.2 6.575,32.7 6.575,35.525 8.564,37.514 8.914,37.514 9.775,38.375 9.775,38.775 11.175,40.175 12.275,40.175 16.3,36.15 16.3,35.8 v1(16.75,35.35)
  Bottom Layer w0.175: v1(5.925,17.276) v1@5.899,17.276 ; 6.237,14.087 5.85,13.7 5.843,13.693 5.843,11.385 6.2,11.027 6.2,9.825 P201.5@6.475,9.55 ; 6.237,14.1 6.237,14.716 6.375,14.853 6.375,16.8 v1@5.899,17.276 ; TPJ8.1@16.6,30.325 16.674,30.325 18.088,31.739 18.088,31.988 18.538,32.438 18.538,34.862 18.212,35.188 16.862,35.188 16.635,35.415 P200.22@16.635,36.45 ; v1@5.899,17.276 5.763,17.276 5.831,17.344 v1@5.899,17.276
  Bottom Layer w0.5: P200.22@16.65,36 16.75,35.9 v1(16.75,35.35)
EFR32_PA1: P200.14 P201.23 TPJ2.1 U1.30 | length 56.9
  Top Layer w0.175: v1@7.275,25.4 7.812,25.4 8.025,25.613 8.57,25.613 9.055,25.127 9.073,25.127 ; 9.075,25.125 9.073,25.127 ; U1.30@9.54,25.1 9.513,25.127 9.073,25.127
  Signal Layer 3 w0.1: v1(7.225,25.4) 7.35,25.525 7.35,27.3 7.8,27.75 7.8,30.65 8.25,31.1 8.25,32.897 v1@10.3,34.947 ; v1(10.275,35) 10.3,34.975 v1@10.3,34.947 ; v1(17.75,11) 17.75,12.95 18.4,13.6 ; 18.401,13.6 18.401,14.724 17.675,15.45 14.967,15.45 14.575,15.842 14.575,17.875 15.375,18.675 17.225,18.675 17.6,19.05 17.6,24.262 19.75,26.412 19.75,28.3 20.375,28.925 20.375,29.425 20.046,29.754 20.046,30.596 v1(20.125,30.675) ; v1@20.162,30.712 19.875,31 19.875,32.425 19.4,32.9 19.175,32.9 18.925,33.15 15.8,33.15 15.575,33.375 12.425,33.375 11.975,33.825 11.125,33.825 10.3,34.65 v1@10.3,34.947
  Bottom Layer w0.175: v1@10.25,35.15 10.3,35.1 10.633,35.1 11.083,35.55 11.324,35.55 P200.14@11.555,35.781 ; v1@17.75,10.8 17.75,9.705 P201.23@17.905,9.55 ; TPJ2.1@19.1,30.875 19.175,30.8 20,30.8 v1(20.125,30.675)
EFR32_PA2: P200.13 P201.21 TPJ1.1 U1.31 | length 36.6
  Top Layer w0.175: v1@8.336,25.025 8.662,25.025 8.91,24.777 8.924,24.777 8.974,24.727 U1.31@9.375,24.727
  Signal Layer 3 w0.1: v1(11.15,32.7) 11.075,32.775 9.295,32.775 9.05,32.53 9.05,30.6 8.625,30.175 8.625,25.4 v1(8.325,25.1) 8.1,24.875 8.1,24.1 9.075,23.125 9.075,19.258 8.775,18.958 8.775,18.125 9.075,17.825 9.075,16.792 10.875,14.992 10.875,14.714 11.339,14.25 13.675,14.25 13.875,14.45 15.091,14.45 15.141,14.4 15.45,14.4 v1@15.675,14.175 ; v1@15.662,14.163 15.675,14.15 v1@15.75,14.15 ; v1@17.2,11.075 16.925,11.075 17.05,11.2 17.05,13 17.926,13.876 v1@18.001,13.876
  Bottom Layer w0.175: v1@15.787,14.063 18.013,14.063 TPJ1.1@18.65,14.7 ; P201.21@16.635,9.55 16.925,9.84 16.925,10.94 16.985,11 v1@17.04,11
  other v1: 17.05,11 18,13.925 15.7,14.225
EFR32_PA3: P200.9 P200.15 P201.19 TPJ3.1 U1.32 | length 43.5
  Top Layer w0.175: v1@8.7,24.3 U1.32@9.54,24.3
  Signal Layer 3 w0.1: v1@9.55,32.275 9.5,32.275 9.3,32.075 9.3,30.425 8.9,30.025 8.9,24.838 v1(8.513,24.45) 9.35,23.613 9.35,19.25 8.975,18.875 8.975,18.225 9.3,17.9 9.3,16.85 11.075,15.075 11.075,14.797 11.422,14.45 13.592,14.45 13.867,14.725 14.65,14.725 15.151,15.226 17.299,15.226 17.8,14.725 17.8,14.3 16.35,12.85 v1(16.35,11)
  Bottom Layer w0.175: P200.9@9.015,33.55 9.015,32.885 v1(9.625,32.275) 9.713,32.187 11.312,32.187 11.85,31.65 12.375,31.65 12.875,32.15 P200.15@12.875,33.3 ; P200.15@12.55,33.275 P200.15@12.825,33.55 ; P201.19@15.365,9.55 15.365,10.215 16.15,11 v1(16.35,11) ; v1@17.85,14.775 17.85,15.08 18.275,15.505 18.275,16.125 18.7,16.55 TPJ3.1@18.7,17.3
  other v1: 17.825,14.65
EFR32_PA4: P200.8 P200.16 P201.17 TPJ4.1 U1.33 | length 68.5
  Top Layer w0.175: v1@6.45,24.775 7.45,24.775 8.3,23.925 U1.33@9.6,23.925
  Signal Layer 3 w0.1: 12.541,12.95 11.963,12.95 11.563,13.35 11.108,13.35 10.075,14.383 10.075,14.661 8.483,16.253 8.297,16.253 7.475,17.075 7.475,21.3 7.075,21.7 7.075,22.35 6.925,22.5 6.925,24.125 6.4,24.65 v1(6.4,24.775) 6.4,25.95 6.25,26.1 6.25,27.9 6.6,28.25 6.6,30.275 7.725,31.4 7.725,34.2 7.875,34.35 7.875,35.1 8.35,35.575 9.152,35.575 v1(12.202,38.625) 12.685,38.142 12.685,34.665 13.425,33.925 15.825,33.925 16.05,33.7 19.125,33.7 19.425,33.4 21.675,33.4 22.375,32.7 22.375,31.45 22.15,31.225 22.15,25.7 21.925,25.475 v1@21.925,24.95 ; 12.541,12.951 12.849,12.951 14.776,11.024 v1(14.776,11.001)
  Bottom Layer w0.1: P200.8@7.745,36.45 P200.8@7.85,36.345
  Bottom Layer w0.175: v1@7.85,35.125 P200.8@7.85,36.345 ; v1@12.175,38.575 12.825,37.925 P200.16@12.825,36.45 ; P201.17@14.37,9.525 14.37,10.445 v1@14.775,10.85 ; TPJ4.1@20.05,25.55 21.3,25.55 21.9,24.95 v1(21.875,24.95)
  other v1: 7.85,35
EFR32_PA5: P200.10 P201.7 U1.34 | length 40.9
  Top Layer w0.175: v1(4,24.526) 5.725,24.525 6,24.25 7.48,24.25 8.155,23.575 9.018,23.575 9.093,23.5 U1.34@9.54,23.5
  Signal Layer 3 w0.1: v1(4,24.526) v1@3.975,24.501 ; v1(7.675,38.275) 5.2,35.8 5.2,32.5 3.25,30.55 3.25,25.3 3.975,24.575 v1@3.975,24.501 ; v1(8.2,10.35) 8.425,10.575 8.425,11.325 7.6,12.15 7.6,12.958 6.425,14.133 6.425,15.526 4.55,17.401 4.55,17.914 3.45,19.014 3.45,19.825 3.6,19.975 3.6,22.836 3.5,22.935 3.5,24.027 v1@3.975,24.501
  Bottom Layer w0.175: v1@7.862,38.262 8.088,38.262 8.725,37.625 8.725,36.74 P200.10@9.015,36.45
EFR32_PA6: P200.11 P201.11 U1.35 | length 46.9
  Top Layer w0.175: v1@4.05,23.101 4.05,23.476 4.474,23.9 4.976,23.9 7.289,23.9 ; 7.313,23.899 7.331,23.899 8.005,23.225 8.85,23.225 8.975,23.1 U1.35@9.54,23.1
  Signal Layer 3 w0.1: v1(3.9,23.101) 3.9,19.85 3.675,19.625 3.675,19.15 4.775,18.05 4.775,17.459 6.625,15.609 6.625,14.216 9.866,10.975 v1(9.9,10.975) ; v1@3.95,23.151 4.025,23.226 4.025,23.8 4.4,24.175 4.4,24.75 3.5,25.65 3.5,30.45 5.475,32.425 5.475,35.3 v1@8.963,38.788
  Bottom Layer w0.1: P200.11@10.285,33.55 P200.11@10.285,34.19
  Bottom Layer w0.175: v1(8.85,38.725) 8.85,38.328 9.653,37.525 9.653,34.803 9.663,34.812 10.011,34.464 P200.11@10.285,34.19 ; v1@10,10.875 10,9.835 P201.11@10.285,9.55
EFR32_PA7: P200.12 P201.13 U1.36 | length 45.3
  Top Layer w0.175: v1(4.575,23.226) 4.885,23.536 7.198,23.536 7.86,22.875 8.705,22.875 8.853,22.727 9.513,22.727 U1.36@9.54,22.7
  Signal Layer 3 w0.1: v1@9.65,39 9.45,39 9.45,38.55 8.975,38.075 8.625,38.075 6.3,35.75 6.3,32.85 3.759,30.309 3.759,25.716 4.649,24.826 4.649,23.226 v1(4.575,23.226) 4.575,23.158 4.15,22.733 4.15,19.917 5.05,19.017 5.05,17.467 6.825,15.692 6.825,14.299 9.524,11.6 10,11.6 v1@10.624,10.976 ; v1(10.576,10.976) v1@10.624,10.976 ; v1@10.675,10.925 v1@10.625,10.975
  Bottom Layer w0.175: v1@9.45,39.1 9.45,38.25 10.025,37.675 10.025,36.71 P200.12@10.285,36.45 P200.12@10.175,36.34 ; v1(10.576,10.976) v1@10.626,10.976 ; v1@10.626,10.975 11.113,10.487 11.363,10.487 11.525,10.325 11.525,9.58 P201.13@11.555,9.55 ; v1@10.725,10.925 v1@10.65,11 ; v1@10.65,11 10.626,10.976 v1@10.65,11
  other v1: 9.475,39.1
EFR32_PA8: P200.19 P201.12 TPJ5.1 U1.37 | length 53.1
  Top Layer w0.175: v1(4.95,22.425) v1@4.962,22.437 ; v1@4.95,22.45 4.95,22.775 5.338,23.164 7.076,23.164 7.74,22.5 8.425,22.5 v1@8.525,22.4 ; v1@8.525,22.3 U1.37@9.54,22.3
  Signal Layer 3 w0.1: v1@5,22.475 v1(4.95,22.425) 4.625,22.1 4.625,20.875 4.875,20.625 4.875,19.8 6.35,18.325 6.35,16.45 7.025,15.775 7.025,14.381 9.531,11.875 10.475,11.875 11.35,11 v1(11.325,11) ; v1@8.5,22.5 8.5,23.25 7.875,23.875 7.875,25.5 8.35,25.975 8.35,30.35 8.775,30.775 8.775,32.644 9.356,33.225 11.6,33.225 12.025,32.8 15.375,32.8 15.55,32.625 16,32.625 v1@16.45,32.175 ; v1(16.5,32.125) 16.85,32.475 17.75,32.475 18.05,32.175 18.05,31.85 19.775,30.125 19.775,29.2 v1@19.875,29.1
  Bottom Layer w0.1: P201.12@10.285,11.89 P201.12@10.285,12.45
  Bottom Layer w0.175: P201.12@10.285,11.89 10.662,11.513 10.787,11.513 v1@11.3,11 ; P200.19@15.6,32.675 15.6,32.65 15.625,32.625 16.1,32.15 16.45,32.15 v1@16.475,32.175 ; TPJ5.1@16.55,25.7 16.55,25.75 16.914,26.114 16.963,26.114 18.253,27.403 18.403,27.403 19.258,28.258 19.258,28.433 19.575,28.75 v1@19.875,29.05
  other v1: 8.5,22.35 19.9,29.125
EFR32_PA9: P200.20 P201.14 TPJ6.1 U1.38 | length 71
  Top Layer w0.175: v1@5.738,22.788 6.957,22.788 7.488,22.257 7.488,22.24 7.577,22.15 7.975,22.15 8.313,21.813 8.911,21.813 8.998,21.9 U1.38@9.54,21.9
  Signal Layer 3 w0.1: v1@11.527,39.475 11.502,39.45 11.175,39.45 10.275,38.55 10.275,37.725 8.95,36.4 8.275,36.4 7.15,35.275 7.15,31.55 5.025,29.425 5.025,27.891 4.725,27.591 4.725,25.475 5.25,24.95 5.25,23.6 5.65,23.2 5.65,20.925 5.175,20.45 5.175,19.85 6.575,18.45 6.575,16.65 7.225,16 7.225,14.464 9.539,12.15 10.95,12.15 12.1,11 v1@12.1,10.975 ; v1@11.55,39.45 12.05,39.45 12.96,38.54 12.96,35.19 13.95,34.2 15.95,34.2 16.175,33.975 19.375,33.975 19.625,33.725 21.8,33.725 22.75,32.775 22.75,31.4 22.375,31.025 22.375,30.2 v1@22.675,29.9 ; v1@22.675,29.875 v1(22.7,29.875)
  Bottom Layer w0.1: P201.14@11.48,13.15 11.48,11.845 12,11.325 v1(12,11)
  Bottom Layer w0.175: v1@11.388,39.488 13.062,39.488 15.075,37.475 15.075,37.275 15.365,36.985 P200.20@15.365,36.45 ; TPJ6.1@20.02,28.07 21.825,29.875 v1(22.7,29.875)
  other v1: 5.6,22.65 11.551,39.452
EFR32_PA10: P200.21 P201.3 TPJ7.1 U1.39 | length 63.5
  Top Layer w0.175: v1(3.2,22.425) 3.213,22.437 4,22.437 4.525,21.912 5.687,21.912 6.213,22.438 6.812,22.438 7.138,22.112 7.138,22.095 7.432,21.8 7.83,21.8 8.168,21.463 9.056,21.463 9.066,21.473 9.067,21.473 9.097,21.503 9.1,21.5 U1.39@9.54,21.5
  Signal Layer 3 w0.1: v1@3.15,22.3 3.2,22.25 3.2,18.9 4.275,17.825 4.275,17.35 5.8,15.825 v1@5.8,15.302 ; v1(3.2,22.425) 3.2,24.785 2.95,25.035 2.95,30.625 4.95,32.625 4.95,36.2 7.875,39.125 8.675,39.125 10.05,40.5 12.325,40.5 17.225,35.6 17.225,35 v1@16.975,34.75 ; v1(17.576,31.952) 17.527,31.952 17.45,31.875 17.475,31.85 19.425,29.9 19.4,29.875 v1(19.35,29.875)
  Bottom Layer w0.175: P201.3@5.205,9.55 5.205,10.095 4.573,10.727 4.573,13.648 5.2,14.275 5.2,14.875 5.65,15.325 v1@5.675,15.325 ; P200.21@16.6,32.9 16.725,33.025 16.725,33.175 16.725,34.563 ; P200.21@16.8,33.25 16.8,32.727 v1(17.576,31.952) ; TPJ7.1@17.659,28.284 17.49,28.115 TPJ7.1@17.49,28.03 18.454,28.03 18.875,28.451 18.875,28.725 19.325,29.175 19.325,29.8 v1@19.375,29.85
  Bottom Layer w0.5: P200.21@16.7,33.2 16.725,33.175 P200.21@16.751,33.149
  other v1: 5.8,15.376 16.975,34.65
EFR32_PA11: P200.18 P201.18 U1.40 | length 43.6
  Top Layer w0.175: v1@6.7,21.775 6.775,21.775 7.1,21.45 7.675,21.45 8.025,21.1 9.2,21.1 U1.40@9.525,21.1
  Signal Layer 3 w0.1: v1(11.2,38.825) 11.2,38.05 9.025,35.875 8.125,35.875 7.4,35.15 7.4,31.45 6.35,30.4 6.35,28.5 6,28.15 6,27.2 5.575,26.775 5.575,25.6 6,25.175 6,24.375 6.625,23.75 v1(6.625,21.9) 6.625,20.175 7.2,19.6 7.2,17.025 8.172,16.053 8.4,16.053 9.875,14.578 9.875,14.3 11.075,13.1 11.53,13.1 12.058,12.572 12.603,12.572 14.1,11.075 v1(14.1,11)
  Bottom Layer w0.1: v1@14.095,11.08 P201.18@14.095,12.45
  Bottom Layer w0.175: v1(11.2,38.825) 11.677,38.825 11.99,39.138 12.487,39.138 13.212,38.413 13.212,37.788 13.625,37.375 13.8,37.375 P200.18@14.025,37.15
EFR32_PB00: P200.25 P201.20 U1.28 | length 40.8
  Top Layer w0.175: v1(7.85,26.475) 7.875,26.45 U1.28@10.375,26.45
  Signal Layer 3 w0.1: v1@14.162,13.875 v1(13.95,13.875) 13.55,13.875 13.4,14.025 11.281,14.025 10.675,14.631 10.675,14.909 8.853,16.731 8.853,17.747 8.575,18.025 8.575,19.041 8.8,19.266 8.8,21.325 8.05,22.075 8.05,23.15 7.675,23.525 7.675,26.05 7.85,26.225 v1(7.85,26.475) 7.85,27.1 8.075,27.325 8.075,30.5 8.525,30.95 8.525,32.783 9.242,33.5 11.75,33.5 12.15,33.1 15.475,33.1 15.65,32.925 18.7,32.925 v1@19.3,32.325
  Bottom Layer w0.175: v1@14.15,13.8 14.443,13.8 14.728,13.515 14.985,13.515 15.312,13.187 15.362,13.187 15.365,13.185 P201.20@15.365,12.45
  Bottom Layer w0.5: P200.25@19.2,33.05 19.3,32.95 v1(19.3,32.3)
EFR32_PB01: P200.26 P201.24 U1.27 | length 61
  Top Layer w0.175: v1@4.6,28.15 4.575,28.125 v1(4.575,28.025) 4.575,27.3 5.063,26.812 6.157,26.812 6.42,26.55 v1(6.9,26.55) 6.92,26.55 7.42,27.05 10.507,27.05 10.75,26.807 10.75,26.38 10.748,26.378 10.748,26.335 U1.27@10.775,26.335
  Signal Layer 3 w0.1: v1(4.575,28.025) 4.575,29.375 6.9,31.7 6.9,35.425 8.45,36.975 8.897,36.975 10.025,38.103 10.025,38.65 11.25,39.875 12.013,39.875 13.25,38.638 13.25,35.575 14.3,34.525 16.025,34.525 16.3,34.25 17.275,34.25 17.425,34.4 17.425,34.825 17.716,35.116 19.359,35.116 v1@19.5,34.975 ; v1@6.825,26.55 6.825,26.6 v1@6.9,26.675 ; v1(6.9,26.55) 6.825,26.475 6.825,25.225 7.425,24.625 7.425,23.25 7.725,22.95 7.725,21.905 8.6,21.03 8.6,19.374 8.375,19.149 8.375,17.9 8.625,17.65 8.625,16.676 10.475,14.826 10.475,14.549 11.199,13.825 13.15,13.825 13.575,13.4 14.35,13.4 14.9,13.95 14.9,14.125 v1@14.937,14.162
  Bottom Layer w0.175: v1@14.9,14.125 14.925,14.125 15.337,13.713 17.237,13.713 17.395,13.555 17.662,13.287 17.825,13.287 17.825,12.53 P201.24@17.905,12.45 ; P200.26@19.175,36.425 19.45,36.15 19.45,35.028 19.423,35.002 v1(19.451,35.002)
  other v1: 14.925,14.05
EFR32_PB02: P201.15 U1.26 | length 29.5
  Top Layer w0.175: v1(5.15,27.45) 5.225,27.45 5.513,27.162 7.037,27.162 7.275,27.4 10.652,27.4 11.142,26.909 11.15,26.901 11.15,26.36 U1.26@11.175,26.335
  Signal Layer 3 w0.1: v1(5.15,27.45) 5,27.3 5,25.55 5.5,25.05 5.5,23.825 6.025,23.3 6.025,20.925 5.575,20.475 5.575,19.78 6.775,18.58 6.775,16.8 7.425,16.15 7.425,14.547 9.572,12.4 11.325,12.4 v1@12.675,11.05
  Bottom Layer w0.175: P201.15@12.7,9.55 v1@12.7,11.025
  other v1: 12.7,11
EFR32_PB03: P201.16 U1.25 | length 24.1
  Top Layer w0.175: v1@6.9,27.675 6.9,27.764 10.783,27.764 11.492,27.054 11.5,27.046 11.5,26.873 11.575,26.798 U1.25@11.575,26.335
  Signal Layer 3 w0.1: v1(6.775,27.675) 6.475,27.375 6.475,26.25 6.62,26.105 6.62,25.147 7,24.767 7,24.475 7.175,24.3 7.175,22.775 7.375,22.575 7.375,21.825 7.725,21.475 7.725,17.15 8.422,16.453 8.566,16.453 10.275,14.744 10.275,14.466 11.116,13.625 11.6,13.625 11.875,13.35 v1(12.375,13.35)
  Bottom Layer w0.5: v1(12.375,13.35) 12.701,13.024 P201.16@12.701,12.626
EFR32_PB04: P201.10 U1.24 | length 26
  Top Layer w0.175: v1@5.55,28.025 5.725,28.2 7.025,28.2 7.111,28.114 10.928,28.114 11.842,27.199 11.85,27.191 11.85,27.018 11.975,26.893 U1.24@11.975,26.335
  Signal Layer 3 w0.1: v1@5.45,27.975 v1@5.55,28.075 ; v1(5.55,28.15) v1@5.55,28.075 ; 6.225,23.599 6.225,21.6 6.4,21.425 6.4,20.091 6.975,19.516 6.975,16.925 8.047,15.853 8.317,15.853 9.675,14.495 9.675,14.15 9.475,13.95 v1(9.475,13.5) ; 6.225,23.6 5.75,24.075 5.75,25.125 5.25,25.625 5.25,26.85 5.575,27.175 5.575,28.1 v1@5.55,28.075
  Bottom Layer w0.5: P201.10@9.015,12.45 9.015,13.04 v1(9.475,13.5)
EFR32_PB05: P200.27 P201.26 U1.23 | length 56.4
  Top Layer w0.175: v1(7.325,28.626) 7.349,28.626 7.375,28.6 7.475,28.7 7.711,28.464 11.073,28.464 12.193,27.344 ; 12.193,27.343 12.2,27.336 12.2,27.163 12.375,26.988 U1.23@12.375,26.335
  Signal Layer 3 w0.1: v1(7.325,28.626) 6.875,29.077 6.875,30.2 7.975,31.3 7.975,33.05 9.65,34.725 9.65,35.2 9.95,35.5 10.45,35.5 10.75,35.2 10.75,34.675 11.275,34.15 12.075,34.15 12.575,33.65 15.75,33.65 15.987,33.413 19.062,33.413 19.347,33.128 19.672,33.128 v1@20.425,32.375 ; v1@20.401,11.1 20.401,11.001 20.375,10.975 20.375,11.65 21.95,13.225 21.95,16.775 23.75,18.575 23.75,19.925 23.275,20.4 23.275,21.471 22.784,21.962 22.549,21.962 21.925,22.587 21.925,23.604 21.475,24.054 21.475,25.325 21.95,25.8 21.95,31.45 22.1,31.6 22.1,32.55 21.825,32.825 20.9,32.825 v1(20.45,32.375)
  Bottom Layer w0.1: P200.27@20.45,33.175 P200.27@20.475,33.2
  Bottom Layer w0.175: P201.26@19.175,12.45 19.175,11.8 19.974,11.001 v1(20.401,11.001)
  Bottom Layer w0.5: v1(20.45,32.375) P200.27@20.45,33.175
EFR32_PC00: RP200.1 U1.1 U100.D2 | length 4.7
  Top Layer w0.175: U1.1@16.41,20.3 16.8,20.3 17.825,19.275 19.45,19.275 19.575,19.4 U100.D2@19.95,19.4
  Bottom Layer w0.3: v2@17.1,20 v2@17.137,19.963 ; RP200.1@17.45,19.575 17.1,19.925 v2@17.137,19.963 ; v2@17.137,19.963 17.15,19.975 v2(17.175,19.975) 17.15,19.95 v2@17.137,19.963
EFR32_PC01: RP200.4 U1.2 U100.C3 | length 5.7
  Top Layer w0.175: U1.2@16.5,20.7 17.2,20.7 18.074,19.826 v2(19.201,19.826) ; U100.C3@20.15,19.05 20.15,18.7 v2@20.25,18.6
  Signal Layer 3 w0.1: v2(19.201,19.826) 19.201,19.474 v2@20.275,18.4
  Bottom Layer w0.3: RP200.4@18.987,19.613 v2@19.175,19.8
  other v2: 20.3,18.575
EFR32_PC02: RP200.2 U1.3 U100.E1 | length 6.4
  Top Layer w0.175: U1.3@16.425,21.1 16.452,21.073 17.322,21.073 18.045,20.35 19.525,20.35 v2@19.725,20.15 ; U100.E1@19.75,19.75 v2@19.75,20.175
  Bottom Layer w0.175: RP200.2@18,19.55 18,19.804 18.546,20.35 19.55,20.35 v2@19.75,20.15
  other v2: 19.8,20.175
EFR32_PC03: R103.1 U1.4 U100.A3 | length 8.9
  Top Layer w0.175: U1.4@16.41,21.5 16.437,21.473 17.417,21.473 18.177,20.712 20.863,20.712 v2@21.125,20.45 ; U100.A3@20.575,19.05 20.793,18.832 21.368,18.832 v2@21.475,18.725 ; v2(21.6,18.725) 21.6,18.702 21.613,18.688 21.625,18.7 21.925,19 R103.1@21.925,19.175 ; v2@21.625,18.625 v2@21.65,18.625
  Signal Layer 3 w0.1: v2@21.175,20.425 21.575,20.025 21.575,18.575 v2@21.55,18.55
  other v2: 21.15,20.45
EFR32_PC04: P200.29 P201.38 U1.5 | length 32.9
  Top Layer w0.175: U1.5@16.41,21.9 16.437,21.873 17.512,21.873 18.322,21.062 21.762,21.062 22.025,21.325 v2(22.85,21.325) 23.2,21.675 v1(24.95,21.675)
  Signal Layer 3 w0.1: v1(21.625,32.375) 21.75,32.25 21.75,25.883 21.275,25.408 21.275,23.875 21.675,23.475 21.675,22.5 v2(22.85,21.325) ; v1(24.95,21.675) 24.95,21.225 25.35,20.825 25.35,18.25 24.575,17.475 24.575,15.227 25.652,14.15 v1(26.075,14.15)
  Bottom Layer w0.1: P201.38@26.795,12.45 P201.38@26.795,13.08
  Bottom Layer w0.175: v1(26.075,14.15) 26.075,13.8 P201.38@26.795,13.08
  Bottom Layer w0.5: v1(21.625,32.375) 21.625,33.275 P200.29@21.675,33.325
EFR32_PC05: P200.28 P201.36 U1.6 | length 41.1
  Top Layer w0.175: U1.6@16.41,22.3 17.58,22.3 18.467,21.412 21.512,21.412 22.062,21.962 22.862,21.962 v1(23.9,23)
  Signal Layer 3 w0.1: v1(19.75,37.8) 19.775,37.775 21.5,37.775 24.025,35.25 24.025,29.2 23.05,28.225 23.05,24.575 23.575,24.05 23.575,23.325 v1(23.9,23) 24.375,22.525 24.375,21.05 25.05,20.375 25.05,18.3 24.25,17.5 24.25,15.077 v1@25.525,13.802 ; 25.05,14.277 v1@25.525,13.802 ; v1(25.525,13.7) v1@25.525,13.802
  Bottom Layer w0.1: P200.28@20.445,36.45 P200.28@20.445,37.08
  Bottom Layer w0.175: v1@19.7,37.825 P200.28@20.445,37.08
  Bottom Layer w0.5: P201.36@25.525,12.45 v1(25.525,13.7)
EFR32_PC06: P200.23 P201.30 U1.7 | length 40.2
  Top Layer w0.175: U1.7@16.41,22.7 17.675,22.7 18.612,21.762 21.213,21.762 21.975,22.525 22.6,22.525 v1(22.65,22.475)
  Signal Layer 3 w0.1: v1(17.875,34.65) 19.128,34.65 19.678,34.1 22,34.1 23.2,32.9 23.2,29.75 22.375,28.925 22.375,23.675 22.175,23.475 22.175,22.925 22.625,22.475 v1(22.65,22.475) ; v1(21.725,11) 21.725,11.025 22.2,11.5 22.2,16.675 24.05,18.525 24.05,20.075 23.55,20.575 23.55,21.525 22.575,22.5 v1@22.425,22.5
  Bottom Layer w0.175: P200.23@17.905,33.55 P200.23@17.905,34.03 ; v1@21.715,11.01 P201.30@21.715,12.45
  Bottom Layer w0.5: P200.23@17.85,33.675 17.875,33.7 v1(17.875,34.65)
EFR32_PC07: P200.24 P201.29 U1.9 | length 41.5
  Top Layer w0.175: U1.9@16.41,23.5 16.437,23.473 17.978,23.473 18.2,23.25 18.286,23.164 v1@22.575,23.164
  Signal Layer 3 w0.1: v1(18.576,37.802) 18.576,36.625 20.025,35.176 20.025,34.75 20.275,34.5 22.275,34.5 23.475,33.3 23.475,29.525 22.6,28.65 22.6,23.2 23.825,21.975 23.825,20.75 24.35,20.225 24.35,18.475 22.476,16.601 v1(22.476,11.001)
  Bottom Layer w0.1: P201.29@21.715,9.55 P201.29@21.715,10.239
  Bottom Layer w0.175: P200.24@17.905,36.45 17.905,37.13 v1@18.55,37.775 ; P201.29@21.715,10.239 v1(22.476,11.001)
  other v1: 22.6,23.175
EFR32_PC08: P200.31 P201.32 U1.10 | length 36.8
  Top Layer w0.175: U1.10@16.41,23.9 16.438,23.872 16.902,23.872 16.952,23.823 18.169,23.823 18.466,23.525 21.05,23.525 21.225,23.7 23.1,23.7 v2(23.125,23.725) 23.225,23.725 23.25,23.7 v2@23.125,23.7
  Signal Layer 3 w0.1: v2@23.075,23.775 22.825,24.025 22.825,28.45 23.75,29.375 23.75,33.625 23.525,33.85 v1@23.525,34.85 ; v2@23.15,23.775 23.15,23.1 24.1,22.15 24.1,20.9 24.75,20.25 24.75,18.45 23.875,17.575 23.875,15 24.75,14.125 24.75,11.502 v1(24.25,11.002)
  Bottom Layer w0.1: P201.32@22.985,11.84 P201.32@22.985,12.45
  Bottom Layer w0.175: P201.32@22.985,11.84 23.823,11.002 v1(24.25,11.002) ; P200.31@22.985,33.55 22.985,34.21 v1@23.47,34.695
  other v1: 23.55,34.85
EFR32_PC09: R329.1 U1.11 | length 8.6
  Top Layer w0.175: U1.11@16.41,24.3 16.437,24.273 U1.11@16.752,24.273 ; U1.11@16.75,24.275 U1.11@16.752,24.273 ; R329.1@20.725,26.45 20.8,26.375 20.99,26.565 v1(20.99,27.005) ; v1@20.975,24.05 v1(20.85,24.05) 20.775,24.05 20.6,23.875 18.611,23.875 18.314,24.173 17.152,24.173 17.052,24.273 U1.11@16.752,24.273
  Signal Layer 3 w0.1: v1(20.85,24.05) 20.9,24.1 20.9,26.915 v1(20.99,27.005)
EFR32_PD00: U1.56 X2.1 | length 2.6
  Top Layer w0.175: U1.56@15.575,19.15 15.6,19.125 U1.56@15.65,19.125 ; U1.56@15.575,19.2 U1.56@15.65,19.125 ; X2.1@17.85,18.55 17.095,18.55 16.757,18.888 16.167,18.888 15.932,19.123 15.653,19.123 U1.56@15.65,19.125
EFR32_PD01: U1.55 X2.2 | length 4.9
  Top Layer w0.175: U1.55@15.193,19.447 U1.55@15.175,19.465 15.175,19.018 15.421,18.772 15.787,18.772 16.022,18.538 16.612,18.538 16.913,18.237 16.913,17.946 17.45,17.408 17.45,16.75 17.525,16.825 X2.2@18.1,16.825
EFR32_PD02: R223.2 R224.1 U1.54 | length 22.5
  Top Layer w0.175: U1.54@14.775,19.465 14.775,18.923 15.448,18.25 15.457,18.26 v1(15.575,18.26)
  Signal Layer 3 w0.1: v1@12.175,8.25 13.2,9.275 15.425,9.275 16.675,10.525 17.9,10.525 18.2,10.825 18.2,12.725 18.675,13.2 18.675,14.875 17.9,15.65 15.175,15.65 14.8,16.025 14.8,17.485 v1(15.575,18.26)
  Bottom Layer w0.175: R224.1@10.575,6.575 R223.2@10.575,7.15 11.05,7.15 12.157,8.257 v1(12.19,8.257)
EFR32_PD03: P200.33 P201.28 U1.53 | length 32.1
  Top Layer w0.175: U1.53@14.375,19.465 14.375,18.735 15.363,17.747 15.798,17.747 16.075,18.025 v1(16.4,18.025)
  Signal Layer 3 w0.1: v1@16.425,18 16.925,18 17.375,17.55 18.1,17.55 ; v1(19.701,17.051) 19.701,17.023 19.649,17.075 19.25,17.075 18.775,17.55 18.1,17.55 ; v1(21,31.2) 21,31.225 21.15,31.075 21.15,29.55 20.875,29.275 20.875,28.64 20.29,28.055 20.29,26.115 18.1,23.925 18.1,17.55
  Bottom Layer w0.175: v1@19.624,16.949 19.624,16.624 19.525,16.525 19.525,15.925 19.741,15.709 20.341,15.709 20.625,15.425 20.625,12.63 P201.28@20.445,12.45 ; v1(21,31.2) 21.55,31.2 22.5,32.15 23.525,32.15 24.255,32.88 P200.33@24.255,33.55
